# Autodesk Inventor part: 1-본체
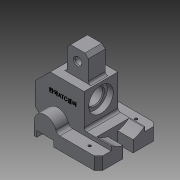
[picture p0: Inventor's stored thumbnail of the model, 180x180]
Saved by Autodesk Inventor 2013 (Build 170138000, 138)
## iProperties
Created: 2016-11
Part Number: 1-본체
Material: 일반
Document SubType Name: Modeling
Designer: default
Density: 1 g/cm^3
Author: default
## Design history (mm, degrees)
sketch "스케치1"
  geometry: L1 (-38, -35)-(38, -35); L2 (38, -35)-(38, 35); L3 (38, 35)-(-38, 35); L4 (-38, 35)-(-38, -35); L5 (-38, -35)-(38, 35); L6 (38, -35)-(-38, 35); 1 further point
  constraints: 12 end point, 2 midpoint, 2 parallel, 1 horizontal, 1 perpendicular
  dimensions: "d0" = 76 distance of L1.start L1.end; "d2" = 70 distance of L3.end L1.start
extrude "돌출1" new body sketch "스케치1" distance "d3" = 15; taper "d4" = 0 deg
sketch "스케치2"
  geometry: L1 (0, 0)-(76, 0) reference; L2 (0, 0)-(0, 15) reference; L3 (3, 0)-(23, 0); L4 (23, 0)-(23, 7); L5 (23, 7)-(3, 7); L6 (3, 7)-(3, 0); 1 further point
  constraints: 8 end point, 2 parallel, 1 horizontal, 1 perpendicular, 1 point on line
  dimensions: "d5" = 3 distance between parallel lines of L6 L2; "d6" = 20 distance between parallel lines of L4 L6; "d7" = 7 distance between parallel lines of L1 L5
extrude "돌출2" cut sketch "스케치2" stored distance "d8" = 15; taper "d9" = 0 deg
sketch "스케치3"
  geometry: L1 (0, 0)-(76, 0) reference; L2 (0, -15)-(0, 0) reference; A1 r 13 centre (13, 0) between (26, 0) and (0, 0); 1 further point
  constraints: 2 point on circle, 2 point on line, 1 centre point, 1 end point
  dimensions: "d12" = 13 radius of A1
extrude "돌출3" join sketch "스케치3" distance "d14" = 70; taper "d15" = 0 deg
node "작업 평면1"
sketch "스케치4"
  geometry: L1 (-53, 0)-(-53, 7) reference; L2 (-53, 7)-(-73, 7) reference; L3 (-73, 7)-(-73, 0) reference; L4 (-73, 0)-(-76, 0) reference; L5 (-76, 0)-(-76, 15) reference; L6 (-50, 15)-(0, 15) reference; L7 (0, 15)-(0, 0) reference; L8 (0, 0)-(-53, 0) reference; L9 (-76, 12)-(-90, 12); L10 (-90, 12)-(-90, 42); L11 (-90, 42)-(-72, 60); L12 (-72, 60)-(-32, 60); L13 (-32, 60)-(-32, 20); L14 (-32, 20)-(0, 20); L15 (0, 20)-(0, 15); A1 r 13 centre (-63, 15) between (-50, 15) and (-76, 15) reference; 1 further point
  constraints: 14 end point, 5 parallel, 1 perpendicular, 1 point on line
  dimensions: "d16" = 45 deg angle of L12 L11; "d17" = 20 distance between parallel lines of L8 L14; "d18" = 48 distance between parallel lines of L9 L12; "d19" = 58 distance between parallel lines of L13 L10; "d20" = 18 distance from line of L11.end L10; "d21" = 60 distance between parallel lines of L4 L12; "d22" = 90 distance between parallel lines of L7 L10
extrude "돌출4" join sketch "스케치4" stored distance "d23" = 40; taper "d24" = 0 deg
sketch "스케치5"
  geometry: 2 further points
  constraints: 1 horizontal alignment
  dimensions: "d25" = 42 distance of point (60, 20) point (18, 20)
hole "구멍1" sketch "스케치5" at (18, 20) diameter "d26" = 20; stored, may be unused: countersink angle "d30" = 90 deg, drill point angle "d32" = 118 deg; dims "d27" = 6, "d28" = 29, "d29" = 7, "d31" = 8
chamfer "모따기1" distance "d33" = 1; stored, may be unused: second distance "d34" = 2, angle "d35" = 45 deg
sketch "스케치6"
  geometry: L1 (-72, 60)-(-32, 60) reference; L2 (-62, 60)-(-37, 60); L3 (-37, 60)-(-37, 90); L4 (-37, 90)-(-62, 90); L5 (-62, 90)-(-62, 60); L6 (-32, 56.5)-(-32, 27.5) reference; L7 (0, 0)-(-53, 0) reference; 1 further point
  constraints: 8 end point, 2 parallel, 1 horizontal, 1 perpendicular, 1 point on line
  dimensions: "d36" = 5 distance between parallel lines of L6 L3; "d37" = 25 distance of L3.end L4.end; "d38" = 90 distance between parallel lines of L7 L4
extrude "돌출5" join sketch "스케치6" stored distance "d39" = 20; taper "d40" = 0 deg
chamfer "모따기2" distance "d41" = 4; stored, may be unused: second distance "d42" = 2, angle "d43" = 45 deg
sketch "스케치7"
  geometry: L1 (-41, 90)-(-58, 90) reference; L2 (-53, 0)-(-53, 7) reference; L3 (-53, 7)-(-73, 7) reference; L4 (-73, 7)-(-73, 0) reference; L5 (-73, 0)-(-76, 0) reference; L6 (-76, 0)-(-76, 12) reference; L7 (-76, 12)-(-90, 12) reference; L8 (-90, 12)-(-90, 42) reference; L9 (-90, 42)-(-72, 60) reference; L10 (-72, 60)-(-62, 60) reference; L11 (-62, 60)-(-62, 86) reference; L12 (-62, 86)-(-58, 90) reference; L13 (-58, 90)-(-41, 90) reference; L14 (-41, 90)-(-37, 86) reference; L15 (-37, 86)-(-37, 60) reference; L16 (-37, 60)-(-32, 60) reference; L17 (-32, 60)-(-32, 52.5) reference; L18 (-32, 52.5)-(-39, 52.5) reference; L19 (-39, 52.5)-(-39, 46.583) reference; L20 (-40, 42)-(-90, 42) reference; L21 (0, 0)-(-53, 0) reference; L22 (0, 20)-(0, 0) reference; L23 (-32, 20)-(0, 20) reference; L24 (-32, 31.5)-(-32, 20) reference; L25 (-39, 31.5)-(-32, 31.5) reference; L26 (-39, 37.417)-(-39, 31.5) reference; L27 (-62, 60)-(-37, 60) reference; 3 further points
  constraints: 1 midpoint, 1 vertical alignment, 2 other
  dimensions: "d44" = 35 distance from line of L20 point (-49.5, 77)
hole "구멍2" sketch "스케치7" at (-49.5, 77) diameter "d45" = 8; stored, may be unused: countersink angle "d49" = 90 deg, drill point angle "d51" = 118 deg; dims "d46" = 6, "d47" = 4, "d48" = 2, "d50" = 8
chamfer "모따기3" distance "d52" = 1; stored, may be unused: second distance "d53" = 2, angle "d54" = 45 deg
sketch "스케치8"
  geometry: L1 (0, 0)-(0, 70) reference; L2 (0, 70)-(0, 0) reference; L3 (0, 0)-(-15, 0) reference; L4 (-15, 0)-(-15, 15) reference; L5 (-15, 15)-(-20, 15) reference; L6 (-20, 15)-(-20, 55) reference; L7 (-20, 55)-(-15, 55) reference; L8 (-15, 55)-(-15, 70) reference; L9 (-15, 70)-(0, 70) reference; C1 r 29 at (-42, 35); 1 further point
  constraints: 1 centre point
  dimensions: "d55" = 42 distance from line of L1 C1.centre; "d56" = 58 diameter of C1
extrude "돌출6" cut sketch "스케치8" distance "d57" = 18; taper "d58" = 0 deg
sketch "스케치9"
  geometry: L1 (0, 0)-(0, 70) reference; L2 (-13.627, 29)-(0, 29); L3 (-13.627, 41)-(0, 41); A1 r 29 centre (-42, 35) between (-20, 16.106) and (-20, 53.894) reference; 1 further point
  constraints: 4 end point, 2 perpendicular, 2 point on circle, 2 point on line
  dimensions: "d59" = 12 distance between parallel lines of L3 L2; "d60" = 6 distance from line of point (0, 35) L2
extrude "돌출7" cut sketch "스케치9" distance "d61" = 18; taper "d62" = 0 deg
chamfer "모따기4" distance "d63" = 5; stored, may be unused: second distance "d64" = 2, angle "d65" = 45 deg
chamfer "모따기5" distance "d66" = 4; stored, may be unused: second distance "d67" = 2, angle "d68" = 45 deg
sketch "스케치10"
  geometry: L1 (38, -30)-(38, -20) reference; L2 (38, 6)-(38, 30) reference; L3 (33, 35)-(-15, 35) reference; 3 further points
  dimensions: "d69" = 18 distance from line of L1 point (20, -27.5); "d70" = 18 distance from line of L2 point (20, 27.5); "d71" = 55 distance of point (20, -27.5) point (20, 27.5); "d72" = 7.5 distance from line of point (20, 27.5) L3
hole "구멍3" sketch "스케치10" at (20, -27.5), (20, 27.5) diameter "d73" = 3.242; stored, may be unused: countersink angle "d77" = 90 deg, drill point angle "d79" = 118 deg; dims "d74" = 6, "d75" = 4, "d76" = 2, "d78" = 8
node "작업 평면2"
sketch "스케치11"
  geometry: L1 (-32, 60)-(-72, 60) reference; L2 (-32, 20)-(-32, 60) reference; 2 further points
  constraints: 1 other
  dimensions: "d81" = 18 distance from line of point (-57, 42) L1; "d82" = 25 distance from line of L2 point (-57, 42)
feature "엠보싱1" sketch "스케치11" dims "d0" = 76, "d2" = 70, "d83" = 0.5, "d84" = 0
fillet "모깎기1" dims "d85" = 5
fillet "모깎기2" dims "d86" = 3
node "솔리드1"
node "절단 모서리 투영1"
node "절단 모서리 투영2"
node "절단 모서리 투영3"
other parameters: "d10" = 26
